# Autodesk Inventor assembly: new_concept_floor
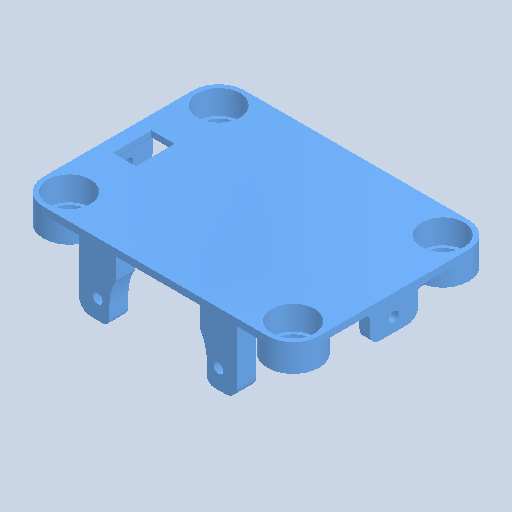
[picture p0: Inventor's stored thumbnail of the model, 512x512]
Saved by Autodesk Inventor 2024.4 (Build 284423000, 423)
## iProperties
Created: 2025-07
Part Number: new_concept_floor
Document SubType Name: Assembly
Designer: AdminForWorker
Title: new_concept_floor v3
Author: AdminForWorker
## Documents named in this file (2)
- c:\worker\convert-fusion-r03-cosv3\tmp\job-1\5\temp\files\c2717cec-cd30-4e2b-a2e5-52afbc4802da\new_concept_floor v3.iam
- c:\worker\convert-fusion-r03-cosv3\tmp\job-1\5\temp\files\c2717cec-cd30-4e2b-a2e5-52afbc4802da\Part6.ipt
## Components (1 placed, 1 different names)
1. Part6
